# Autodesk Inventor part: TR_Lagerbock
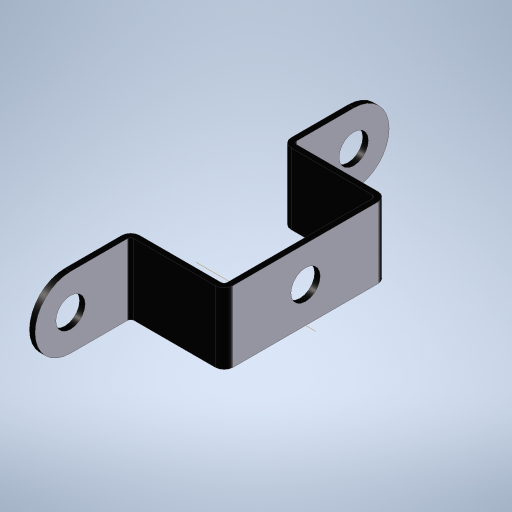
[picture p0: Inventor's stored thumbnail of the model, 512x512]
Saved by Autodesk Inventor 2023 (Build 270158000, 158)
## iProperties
Created: 2023-11
Part Number: TR_Lagerbock
Material: Edelstahl
Document SubType Name: Modeling
Designer: Admin
Density: 8 g/cm^3
Appearance: Halbpoliert
Author: Admin
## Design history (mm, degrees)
sketch "Skizze1"
  geometry: L1 (14, 25)-(13.2, 25); L2 (13.2, 25)-(13.2, 11.95); L3 (12.75, 11.5)-(1.25, 11.5); L4 (0, 10.25)-(0, -10.25); L5 (1.25, -11.5)-(12.75, -11.5); L6 (13.2, -11.95)-(13.2, -25); L7 (13.2, -25)-(14, -25); L8 (14, -25)-(14, -11.95); L9 (12.75, -10.7)-(1.25, -10.7); L10 (0.8, -10.25)-(0.8, 10.25); L11 (1.25, 10.7)-(12.75, 10.7); L12 (14, 11.95)-(14, 25); L13 (17.162, 0)-(-3.162, 0) reference; A1 r 1.25 centre (1.25, 10.25) between (1.25, 11.5) and (0, 10.25); A2 r 1.25 centre (1.25, -10.25) between (0, -10.25) and (1.25, -11.5); A3 r 0.45 centre (1.25, 10.25) between (1.25, 10.7) and (0.8, 10.25); A4 r 0.45 centre (1.25, -10.25) between (0.8, -10.25) and (1.25, -10.7); A5 r 1.25 centre (12.75, 11.95) between (12.75, 10.7) and (14, 11.95); A6 r 1.25 centre (12.75, -11.95) between (14, -11.95) and (12.75, -10.7); A7 r 0.45 centre (12.75, 11.95) between (12.75, 11.5) and (13.2, 11.95); A8 r 0.45 centre (12.75, -11.95) between (13.2, -11.95) and (12.75, -11.5); 7 further points
  constraints: 24 end point, 16 point on circle, 16 tangent, 9 point on line, 8 centre point, 6 perpendicular, 4 equal radius, 3 coincident, 3 horizontal, 3 midpoint, 2 parallel, 1 horizontal alignment, 1 symmetric about line, 1 vertical alignment
  dimensions: "d0" = 0.8 distance of L1.start L1.end (= Dicke); "d1" = 14 horizontal distance of point (0, 0) point (14, 10.7); "d3" = 50 distance of L7.end L1.start; "d4" = 0.8 distance between parallel lines of L11 L3 (= Dicke); "d6" = 1.25 radius of A1 (derived); "d9" = 23 distance between parallel lines of L5 L3; "d10" = 1.25 radius of A5 (derived)
extrude "Extrusion1" new body sketch "Skizze1" distance "d12" = 10 (= Einheitsmaß); taper "d13" = 0 deg
fillet "Rundung1" dims "d14" = 5 (= 0.5 x Einheitsmaß)
sketch "Skizze2"
  geometry: L1 (0, 0)-(20.5, 0) reference; C1 r 2.075 at (-9.75, 5); C2 r 2.075 at (10.25, 5); C3 r 2.075 at (30.25, 5); A1 r 5 centre (-9.75, 5) between (-9.75, 10) and (-9.75, 0) reference; A2 r 5 centre (30.25, 5) between (30.25, 0) and (30.25, 10) reference; 2 further points
  constraints: 3 centre point, 2 coincident, 2 equal radius, 1 horizontal alignment, 1 midpoint, 1 vertical alignment
  dimensions: "d15" = 4.15 diameter of C1 (= 2 x Radius)
extrude "Extrusion2" cut sketch "Skizze2" extent not by distance; stored distance "d16" = 0; taper "d17" = 0 deg
node "Volumenkörper1"
other parameters: "Einheitsmaß" = 10 [user parameter; used in 2 equation terms], "Radius" = 2.075 [user parameter; used in 1 equation term], "Fasen" = 0.5 [user parameter], "Dicke" = 0.8 [user parameter; used in 2 equation terms], "Breitloch" = 2 [user parameter], "Langloch" = 32 [user parameter], "AchteckUmkreis" = 6 [user parameter], "DAchsAufnahme" = 4.1 [user parameter]
